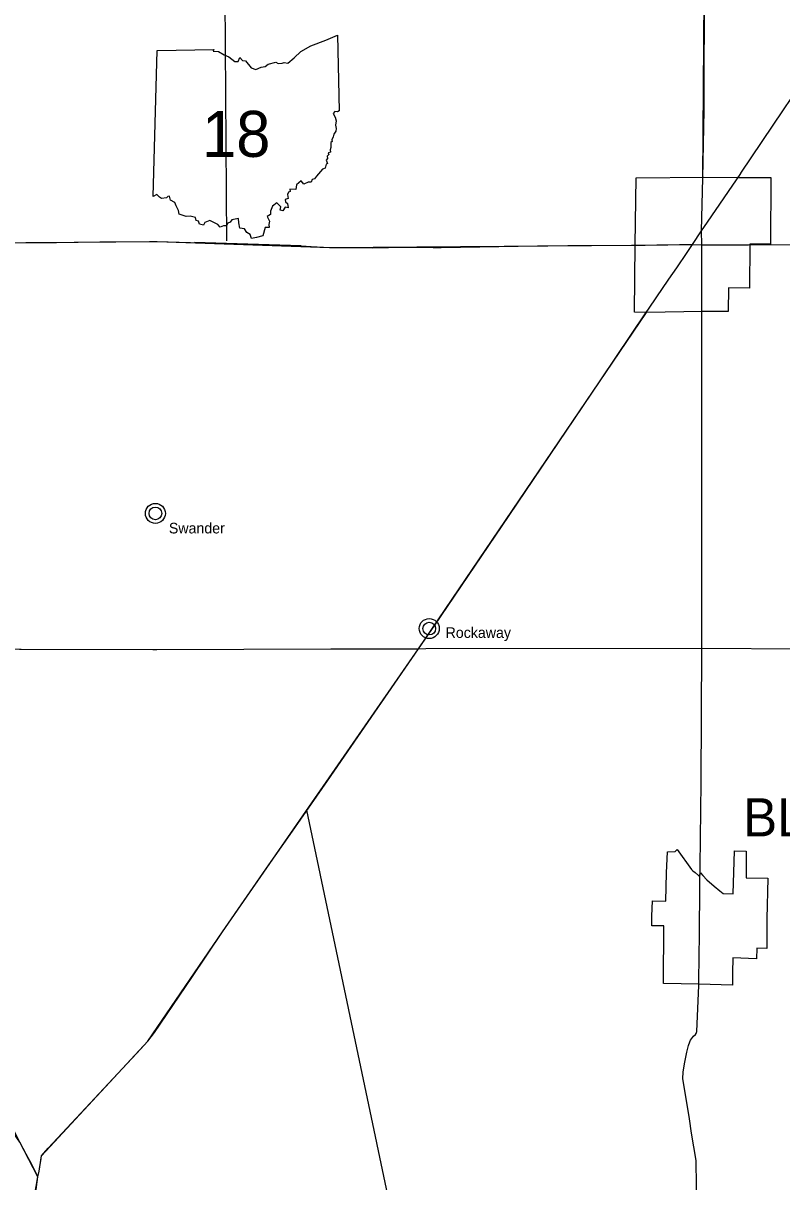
# Model space of a CAD drawing. Extents: x 0 to 882, y 0 to 440.
# Drawn here: x 352.8 to 427.4, y 123.7 to 237.6 of the extents above; entities that cross this region are included whole.
import ezdxf

# ---------------------------------------------------------------- set-up
doc = ezdxf.new("R2010")
doc.units = 0
for name, color, linetype in [('DV_X_Corp_Line', 7, 'Continuous'), ('GM_X_Corporation_Text', 7, 'Continuous'), ('GM_X_State_Route', 7, 'Continuous'), ('GM_X_US_Route', 7, 'Continuous'), ('PV_P_Text', 7, 'Continuous'), ('RD_P_Fence', 7, 'Continuous'), ('SH_Data', 7, 'Continuous')]:
    doc.layers.add(name, color=color, linetype=linetype)

msp = doc.modelspace()

# ---------------------------------------------------------------- linework, layer by layer
at = {"layer": 'DV_X_Corp_Line'}
for points in [[(412.98, 215.79), (413.06, 222.37), (419.71, 222.45), (423.04, 222.41), (426.31, 222.42), (426.26, 215.85), (424.24, 215.85), (424.2, 211.54), (422.15, 211.57), (422.12, 209.25), (419.59, 209.26), (414.08, 209.16), (412.9, 209.18)], [(416.05, 154.06), (416.16, 156.13), (416.91, 156.15), (417.1, 156.36), (418.5, 154.41), (418.64, 154.28), (418.86, 154.09), (419.19, 153.81), (419.27, 153.75), (419.34, 153.73), (419.38, 154.06), (419.63, 153.8), (420.01, 153.39), (420.74, 152.77), (421.31, 152.31), (421.61, 152.04), (422.6, 151.99), (422.75, 156.23), (423.87, 156.19), (423.88, 153.58), (426.02, 153.53), (425.91, 149.56), (425.9, 146.64), (424.94, 146.67), (424.9, 145.61), (422.56, 145.71), (422.56, 145.56), (422.54, 144.41), (422.53, 143.03), (419.24, 143.11), (415.76, 143.19), (415.78, 148.86), (414.61, 148.86), (414.62, 149.82), (414.66, 151.3), (415.99, 151.29)]]:
    msp.add_lwpolyline(points, close=True, dxfattribs=at)
for centre, radius in [((365.79, 189.4), 0.982), ((365.79, 189.4), 0.623), ((392.72, 178.08), 0.982), ((392.72, 178.08), 0.623)]:
    msp.add_circle(centre, radius, dxfattribs=at)
at = {"layer": 'GM_X_State_Route'}
for points in [[(423.36, 222.84), (427.54, 229.08), (432.09, 235.75), (433.12, 237.24), (441.18, 248.94), (446.03, 256.15), (446.36, 256.69), (446.66, 257.11), (447.13, 257.81), (449.99, 261.97), (452.05, 265.01), (454.26, 268.16), (454.83, 268.96), (457.29, 272.53), (459.34, 275.54), (460.09, 276.56), (460.6, 277.23), (461.17, 278), (463.6, 280.26), (465.54, 282.13), (471.41, 287.84)], [(419.61, 222.36), (419.76, 229.03), (419.79, 241.9), (419.85, 249.02), (419.95, 256.52), (420, 256.96), (420.24, 257.98), (420.36, 258.41), (420.36, 269.74)], [(419.52, 215.79), (419.49, 217.16), (419.61, 222.36), (419.61, 222.36)], [(420.08, 218.02), (423.35, 222.82), (423.36, 222.84)], [(418.62, 215.83), (419.49, 217.16), (420.07, 218.02), (420.08, 218.02)], [(335.44, 215.91), (338.63, 215.99), (339.95, 215.99), (353.06, 216.02), (353.75, 216.02)], [(353.75, 216.02), (356.08, 216.03), (360.32, 216.1), (365.2, 216.12), (365.96, 216.12), (380.12, 215.71), (369.65, 216.03)], [(380.12, 215.71), (381.11, 215.64), (382.91, 215.53), (387.16, 215.5), (390.25, 215.56), (393.11, 215.52), (393.89, 215.52), (403.36, 215.71), (406.34, 215.72), (412.6, 215.76), (413.94, 215.77), (413.94, 215.77)], [(413.94, 215.77), (415.11, 215.79)], [(414.05, 209.13), (414.34, 209.56), (415.73, 211.59), (416.16, 212.23), (416.29, 212.42), (417.06, 213.55), (417.32, 213.92), (417.81, 214.65), (418.42, 215.54), (418.62, 215.83)], [(415.11, 215.79), (415.59, 215.8), (416.19, 215.8), (417.33, 215.82), (418.42, 215.83), (418.62, 215.83)], [(418.62, 215.83), (419.52, 215.79), (420.66, 215.8), (424.1, 215.81), (424.11, 215.81)], [(419.53, 209.33), (419.53, 209.36), (419.53, 210.38), (419.53, 211.3), (419.53, 212.44), (419.52, 213.56), (419.52, 214.67), (419.52, 215.79)], [(424.11, 215.81), (425.16, 215.82)], [(425.16, 215.82), (426.19, 215.82), (426.21, 215.82)], [(426.21, 215.82), (432.91, 215.81), (446.37, 215.8)], [(409.58, 202.53), (414.03, 209.1), (414.05, 209.13)], [(419.53, 176.16), (419.53, 189.38), (419.54, 202.61), (419.53, 209.33)], [(407.81, 199.9), (409.58, 202.53)], [(393.21, 178.32), (400.57, 189.2), (407.81, 199.9)], [(391.65, 176.1), (392.99, 178), (393.21, 178.32), (393.21, 178.32)], [(354.55, 125.99), (354.55, 125.99), (354.59, 126.26), (355.26, 127.01), (363.95, 136.31), (365.05, 137.52), (365.7, 138.38), (369.38, 143.78), (372.4, 148.26), (376.94, 154.85), (379.04, 157.84), (382.73, 163.11), (391.65, 176.1)], [(419.36, 154.68), (419.46, 162.94), (419.53, 176.16)], [(419.33, 152.04), (419.33, 152.16), (419.33, 153.64), (419.36, 154.22), (419.36, 154.29)], [(419.36, 154.29), (419.36, 154.61), (419.36, 154.68)], [(419.32, 151.12), (419.33, 151.97), (419.33, 152.04)], [(419.29, 148.07), (419.29, 148.83), (419.3, 149.66), (419.32, 151.05), (419.32, 151.06), (419.32, 151.12)], [(419.27, 146.62), (419.28, 147.21), (419.29, 147.97), (419.29, 148.01), (419.29, 148.07)], [(419.22, 143.05), (419.24, 143.7), (419.26, 145.56), (419.27, 146.55), (419.27, 146.62)], [(418.34, 96.52), (418.48, 102.28), (418.83, 109.89), (418.99, 123.29), (418.97, 125.8), (418.52, 128.47), (418.31, 129.89), (417.67, 133.85), (417.69, 134.46), (417.82, 135.31), (418.05, 136.45), (418.22, 137.09), (418.36, 137.45), (418.41, 137.62), (418.72, 138), (418.9, 138.18), (418.97, 138.29), (419.04, 138.47), (419.22, 142.98), (419.22, 143.05)], [(354.24, 124.19), (353.63, 125.39), (353.45, 125.75), (353.1, 126.4), (352.46, 127.61), (352, 128.51), (351.84, 128.73)], [(354.24, 124.19), (354.37, 124.74), (354.43, 125.19), (354.45, 125.35), (354.55, 125.99)], [(353.74, 121.33), (353.89, 121.63), (353.99, 122.26), (354.11, 123.2), (354.24, 124.19)]]:
    msp.add_lwpolyline(points, dxfattribs=at)
at = {"layer": 'GM_X_US_Route'}
for points in [[(336.78, 176.19), (339.2, 176.18), (352.42, 176.04), (352.6, 176.04), (365.54, 176.01), (365.95, 176.01), (383.03, 176.07)], [(383.03, 176.07), (391.65, 176.1)], [(391.65, 176.1), (392.37, 176.11), (419.53, 176.16)], [(419.53, 176.16), (429.27, 176.1), (432.75, 176.11), (445.97, 176.05), (459.29, 175.89), (472.21, 175.68), (472.55, 175.67), (475.59, 175.64), (479.1, 175.58), (479.38, 175.51), (481.11, 174.68), (498.87, 165.03), (499.8, 164.54)]]:
    msp.add_lwpolyline(points, dxfattribs=at)
at = {"layer": 'PV_P_Text'}
msp.add_line((365.57, 220.54), (365.97, 234.9), dxfattribs=at)
msp.add_line((365.57, 220.54), (365.97, 234.9), dxfattribs=at)
for points in [[(365.97, 234.9), (371.55, 235), (371.46, 234.82), (371.99, 234.79), (372.54, 234.48), (373.02, 234.28), (373.59, 233.83), (373.94, 233.83), (374.09, 234.21), (374.35, 233.92), (374.66, 233.87), (375.21, 233.18), (375.66, 233.03), (376.19, 233.27), (376.59, 233.31), (376.89, 233.54), (377.65, 233.74), (377.87, 233.62), (378.27, 233.64), (378.47, 233.73), (378.83, 233.65), (379.45, 234.17), (380.09, 234.79), (381.07, 235.37), (382.54, 235.92), (383.71, 236.41), (383.87, 228.96)], [(365.97, 234.9), (371.55, 235), (371.46, 234.82), (371.99, 234.79), (372.54, 234.48), (373.02, 234.28), (373.59, 233.83), (373.94, 233.83), (374.09, 234.21), (374.35, 233.92), (374.66, 233.87), (375.21, 233.18), (375.66, 233.03), (376.19, 233.27), (376.59, 233.31), (376.89, 233.54), (377.65, 233.74), (377.87, 233.62), (378.27, 233.64), (378.47, 233.73), (378.83, 233.65), (379.45, 234.17), (380.09, 234.79), (381.07, 235.37), (382.54, 235.92), (383.71, 236.41), (383.87, 228.96)], [(383.87, 228.96), (383.7, 228.86), (383.44, 228.9), (383.26, 228.7), (383.48, 228.35), (383.58, 227.98), (383.49, 227.57), (383.58, 227.24), (383.52, 226.96), (383.35, 226.68), (383.29, 226.41), (383.15, 226.13), (383.16, 225.97), (383.03, 225.85), (383.05, 225.38), (382.98, 225.13), (383.01, 224.9), (382.79, 224.84), (382.84, 224.66), (382.7, 224.52), (382.73, 224.27), (382.57, 224.12), (382.72, 223.8), (382.6, 223.71), (382.49, 223.32), (382.21, 223.25), (381.64, 222.55), (381.44, 222.29), (381.22, 222.22), (381.1, 221.95), (380.82, 221.95), (380.4, 221.77), (380.13, 222.09), (379.66, 221.7), (379.6, 221.25), (379, 221.27), (379.03, 221.04), (378.89, 220.97), (378.77, 220.75), (378.84, 220.34), (378.56, 220.24), (378.59, 220.01), (378.77, 219.86), (378.85, 219.42), (378.56, 219.51), (378.31, 219.13), (378.06, 219.22), (378.14, 219.54), (377.72, 219.92), (377.32, 219.61), (377.11, 219.12), (377.1, 218.79), (376.8, 218.59), (377, 218.13), (376.96, 217.8), (376.97, 217.5), (376.59, 217.51), (376.37, 216.68)], [(383.87, 228.96), (383.7, 228.86), (383.44, 228.9), (383.26, 228.7), (383.48, 228.35), (383.58, 227.98), (383.49, 227.57), (383.58, 227.24), (383.52, 226.96), (383.35, 226.68), (383.29, 226.41), (383.15, 226.13), (383.16, 225.97), (383.03, 225.85), (383.05, 225.38), (382.98, 225.13), (383.01, 224.9), (382.79, 224.84), (382.84, 224.66), (382.7, 224.52), (382.73, 224.27), (382.57, 224.12), (382.72, 223.8), (382.6, 223.71), (382.49, 223.32), (382.21, 223.25), (381.64, 222.55), (381.44, 222.29), (381.22, 222.22), (381.1, 221.95), (380.82, 221.95), (380.4, 221.77), (380.13, 222.09), (379.66, 221.7), (379.6, 221.25), (379, 221.27), (379.03, 221.04), (378.89, 220.97), (378.77, 220.75), (378.84, 220.34), (378.56, 220.24), (378.59, 220.01), (378.77, 219.86), (378.85, 219.42), (378.56, 219.51), (378.31, 219.13), (378.06, 219.22), (378.14, 219.54), (377.72, 219.92), (377.32, 219.61), (377.11, 219.12), (377.1, 218.79), (376.8, 218.59), (377, 218.13), (376.96, 217.8), (376.97, 217.5), (376.59, 217.51), (376.37, 216.68)], [(376.37, 216.68), (375.72, 216.53), (375.26, 216.43), (375.11, 216.81), (374.78, 217), (374.57, 217.38), (374.11, 217.43), (374, 217.95), (373.95, 218.37), (373.31, 218.27), (373.14, 218.01), (372.91, 217.94), (372.78, 217.68), (372.48, 217.66), (372.15, 217.54), (371.93, 217.79), (371.4, 218.05), (371.15, 218.18), (370.65, 217.98), (370.54, 217.73), (370.14, 217.84), (370.04, 218.11), (369.8, 218.19), (369.74, 218.48), (369.22, 218.63), (368.82, 218.57), (368.12, 218.8), (368.08, 219.18), (367.84, 219.63), (367.71, 219.95), (367.27, 220.2), (367.18, 220.57), (367.03, 220.56), (366.9, 220.41), (366.41, 220.34), (366.21, 220.49), (365.94, 220.76), (365.57, 220.54)], [(376.37, 216.68), (375.72, 216.53), (375.26, 216.43), (375.11, 216.81), (374.78, 217), (374.57, 217.38), (374.11, 217.43), (374, 217.95), (373.95, 218.37), (373.31, 218.27), (373.14, 218.01), (372.91, 217.94), (372.78, 217.68), (372.48, 217.66), (372.15, 217.54), (371.93, 217.79), (371.4, 218.05), (371.15, 218.18), (370.65, 217.98), (370.54, 217.73), (370.14, 217.84), (370.04, 218.11), (369.8, 218.19), (369.74, 218.48), (369.22, 218.63), (368.82, 218.57), (368.12, 218.8), (368.08, 219.18), (367.84, 219.63), (367.71, 219.95), (367.27, 220.2), (367.18, 220.57), (367.03, 220.56), (366.9, 220.41), (366.41, 220.34), (366.21, 220.49), (365.94, 220.76), (365.57, 220.54)]]:
    msp.add_lwpolyline(points, dxfattribs=at)
at = {"layer": 'RD_P_Fence'}
msp.add_line((419.61, 222.36), (420.19, 296.37), dxfattribs=at)
for points in [[(353.75, 216.02), (353.75, 216.02), (365.96, 216.12), (382.91, 215.53), (412.98, 215.76)], [(354.37, 124.74), (354.59, 126.26), (365.05, 137.52), (372.4, 148.26), (391.65, 176.1), (414.08, 209.16)], [(364.27, 96.7), (357.65, 109.93), (354.78, 115.84), (353.74, 121.33), (354.24, 124.19), (352.46, 127.61), (341.85, 142.9), (340.8, 144.52), (339.05, 146.23), (338.86, 155.61), (332.91, 159.33), (321.07, 182.72), (316.82, 190.88)]]:
    msp.add_lwpolyline(points, dxfattribs=at)
at = {"layer": 'SH_Data'}
for p, q in [((371.8, 343.11), (372.8, 216.18)), ((395.16, 91.42), (380.67, 160.23))]:
    msp.add_line(p, q, dxfattribs=at)

# ---------------------------------------------------------------- texts
at = {"layer": 'DV_X_Corp_Line'}
for s, p in [('Swander', (367.12, 187.43)), ('Rockaway', (394.33, 177.16))]:
    msp.add_text(s, height=1.042, rotation=0, dxfattribs=at).set_placement(p)
at = {"layer": 'GM_X_Corporation_Text'}
msp.add_text('BLOOMVILLE', height=3.75, rotation=0, dxfattribs=at).set_placement((423.59, 157.65))
at = {"layer": 'PV_P_Text'}
msp.add_text('18', height=4.528, dxfattribs=at).set_placement((370.37, 224.44))

doc.saveas('drawing.dxf')
